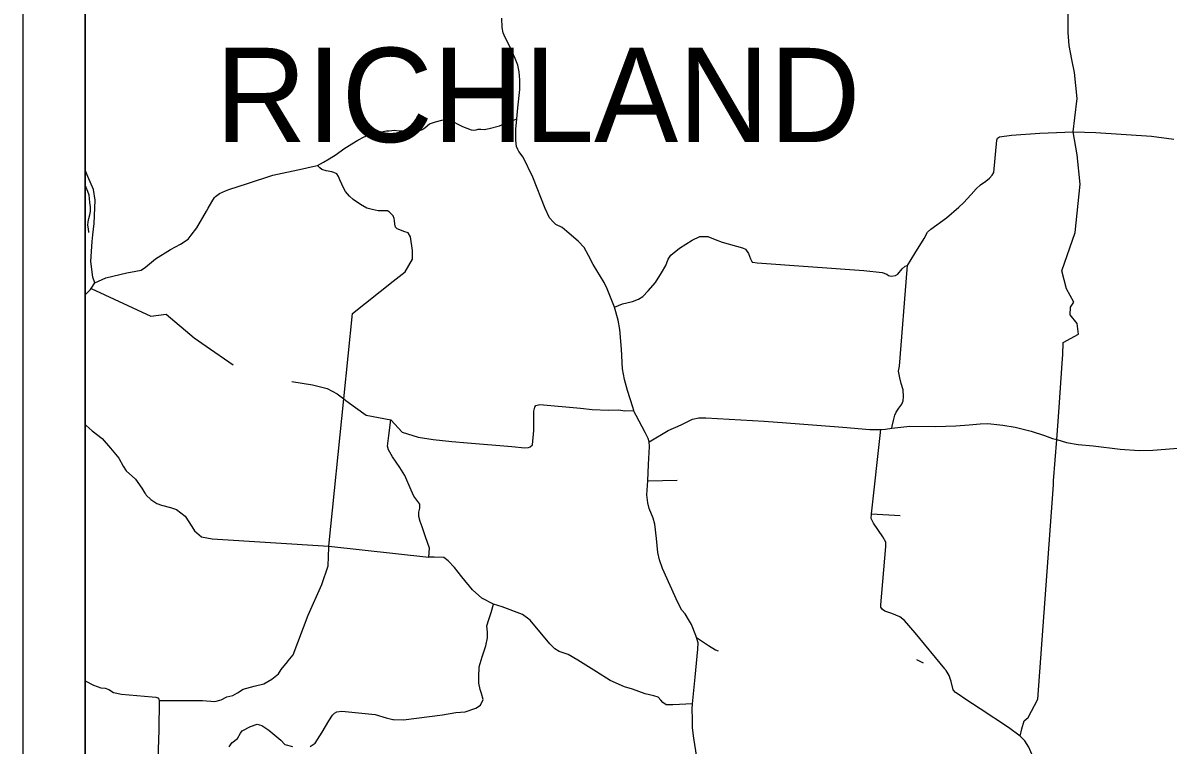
# Model space of a CAD drawing. Extents: x -22 to 431, y -18 to 160.
# Drawn here: x -21.978 to -20.139, y 24.992 to 26.152 of the extents above; entities that cross this region are included whole.
import ezdxf

# ---------------------------------------------------------------- set-up
doc = ezdxf.new("R2010")
doc.units = 0
for name, color, linetype in [('GM_X_Adjacent_County_Text', 7, 'Continuous'), ('GM_X_County_Road', 7, 'Continuous'), ('GM_X_County_Road_Text', 7, 'Continuous'), ('GM_X_County_ROW', 7, 'Continuous'), ('GM_X_Minor_River', 7, 'Continuous'), ('GM_X_Minor_River_Text', 7, 'Continuous'), ('GM_X_Section', 7, 'Continuous'), ('GM_X_Township_Subdivision_Text', 7, 'Continuous')]:
    doc.layers.add(name, color=color, linetype=linetype)

msp = doc.modelspace()

# ---------------------------------------------------------------- linework, layer by layer
at = {"layer": 'GM_X_Adjacent_County_Text'}
for points in [[(-21.8776, 25.7159), (-21.8767, 25.7165), (-21.8689, 25.7237), (-21.8678, 25.7255), (-21.8619, 25.7345), (-21.8654, 25.7436), (-21.8684, 25.769), (-21.8666, 25.8007), (-21.8653, 25.8115), (-21.8632, 25.8297), (-21.8619, 25.8548), (-21.8618, 25.8675), (-21.8644, 25.8845), (-21.8736, 25.9051), (-21.8776, 25.9155)], [(-20.9723, 25.4793), (-20.9414, 25.4974), (-20.9209, 25.5063), (-20.9024, 25.5156), (-20.8925, 25.5177), (-20.881, 25.5179), (-20.7873, 25.5121), (-20.7518, 25.5095), (-20.6613, 25.5025), (-20.6178, 25.4992), (-20.6, 25.499), (-20.5928, 25.4996), (-20.5824, 25.5013), (-20.5534, 25.5041), (-20.5121, 25.504), (-20.4798, 25.505), (-20.4585, 25.5063), (-20.4409, 25.5082), (-20.4283, 25.5088), (-20.4044, 25.506), (-20.3845, 25.5028), (-20.3589, 25.4963), (-20.3375, 25.4891), (-20.3245, 25.4846), (-20.3178, 25.4827), (-20.3021, 25.4782), (-20.2834, 25.4751), (-20.2593, 25.4725), (-20.2157, 25.4676), (-20.1856, 25.4655), (-20.1635, 25.4657), (-20.1163, 25.4694)], [(-21.8776, 25.0951), (-21.8645, 25.0883), (-21.8527, 25.0843), (-21.8457, 25.0834), (-21.8395, 25.0813), (-21.8321, 25.0768), (-21.8192, 25.0741), (-21.7698, 25.0696), (-21.7639, 25.069), (-21.7609, 25.0681), (-21.7594, 25.066), (-21.759, 25.0647), (-21.7586, 25.0635), (-21.7595, 25.0163), (-21.7609, 24.9693)]]:
    msp.add_lwpolyline(points, dxfattribs=at)
at = {"layer": 'GM_X_County_Road'}
for points in [[(-20.3081, 25.6189), (-20.3081, 25.619), (-20.3072, 25.6388), (-20.2826, 25.6523), (-20.2849, 25.669), (-20.2959, 25.6832), (-20.2954, 25.6955), (-20.2901, 25.7035), (-20.3019, 25.7251), (-20.3097, 25.7536), (-20.2884, 25.8154), (-20.2799, 25.8932), (-20.2849, 25.9402), (-20.2916, 25.9769)], [(-21.5516, 25.1273), (-21.5436, 25.1373), (-21.5196, 25.2007), (-21.4977, 25.25), (-21.4875, 25.2798), (-21.4866, 25.3101), (-21.4865, 25.3117), (-21.4623, 25.5482), (-21.4483, 25.6855), (-21.3833, 25.7371), (-21.364, 25.7523), (-21.3522, 25.7724), (-21.3519, 25.7865), (-21.3553, 25.8083), (-21.3591, 25.815), (-21.3658, 25.8171)], [(-21.326, 25.2941), (-21.3249, 25.3082), (-21.331, 25.3265), (-21.3363, 25.3427), (-21.3397, 25.351), (-21.3418, 25.3592), (-21.3417, 25.366), (-21.3402, 25.3726), (-21.3405, 25.3789), (-21.3498, 25.3918), (-21.354, 25.4018), (-21.3643, 25.4251), (-21.3722, 25.438), (-21.3842, 25.4549), (-21.3905, 25.4661), (-21.3924, 25.4722), (-21.3899, 25.4896), (-21.3871, 25.5147)], [(-21.7815, 25.3966), (-21.7795, 25.3934), (-21.7723, 25.3865), (-21.7626, 25.3801), (-21.755, 25.3773), (-21.7408, 25.3739), (-21.731, 25.3705), (-21.7171, 25.36), (-21.7063, 25.343), (-21.702, 25.3361), (-21.691, 25.3267), (-21.6739, 25.3235), (-21.4865, 25.3117)], [(-20.3767, 25.0063), (-20.3736, 25.0182), (-20.3699, 25.0313), (-20.3634, 25.0366), (-20.3481, 25.066), (-20.3231, 25.4099), (-20.3231, 25.4101)], [(-21.5165, 24.9901), (-21.5084, 24.9951), (-21.497, 25.0131), (-21.4864, 25.0309), (-21.4806, 25.0404), (-21.4772, 25.0435), (-21.4738, 25.0457), (-21.4658, 25.0467), (-21.412, 25.041), (-21.3946, 25.0359), (-21.3838, 25.0331), (-21.3829, 25.0331)], [(-21.6464, 24.9895), (-21.6419, 24.9955), (-21.6333, 25.0029), (-21.6284, 25.0113), (-21.6254, 25.0149), (-21.6124, 25.0221), (-21.6016, 25.0255), (-21.5938, 25.0235), (-21.5828, 25.0161), (-21.5635, 24.9998), (-21.5572, 24.9931), (-21.5449, 24.9897)]]:
    msp.add_lwpolyline(points, dxfattribs=at)
at = {"layer": 'GM_X_County_ROW'}
msp.add_lwpolyline([(-20.8938, 24.9625), (-20.9005, 25.0031), (-20.9024, 25.02), (-20.9024, 25.0333), (-20.903, 25.0504), (-20.9023, 25.0585), (-20.8984, 25.1014), (-20.8939, 25.1461), (-20.8935, 25.1564), (-20.8961, 25.1651), (-20.897, 25.1684), (-20.9039, 25.1857), (-20.9088, 25.1937), (-20.9143, 25.2028), (-20.9196, 25.209), (-20.926, 25.2211), (-20.9506, 25.2758), (-20.9554, 25.2896), (-20.9583, 25.3014), (-20.9605, 25.3241), (-20.9628, 25.3467), (-20.9656, 25.3565), (-20.9721, 25.372), (-20.9745, 25.3814), (-20.9758, 25.3939), (-20.9745, 25.4165), (-20.9729, 25.4425), (-20.9715, 25.4717), (-20.9723, 25.4793), (-20.9739, 25.4843), (-20.9786, 25.4939), (-20.9928, 25.5214), (-20.9962, 25.5275), (-20.9968, 25.5294), (-20.9985, 25.5348), (-21.0068, 25.5614), (-21.0119, 25.5795), (-21.0148, 25.5965), (-21.0167, 25.6281), (-21.0192, 25.6598), (-21.0221, 25.6747), (-21.0277, 25.6957), (-21.0395, 25.7251), (-21.0446, 25.7352), (-21.0618, 25.7637), (-21.0696, 25.7783), (-21.0764, 25.7912), (-21.0862, 25.8015), (-21.1042, 25.8169), (-21.1118, 25.8233), (-21.1218, 25.8282), (-21.1261, 25.8325), (-21.132, 25.8391), (-21.1393, 25.8537), (-21.159, 25.9042), (-21.1744, 25.9364), (-21.1811, 25.9457), (-21.1831, 25.9489), (-21.1851, 25.9537), (-21.186, 25.9638), (-21.186, 25.9814), (-21.1846, 25.9977), (-21.1829, 26.0155), (-21.18, 26.0449), (-21.1797, 26.0607), (-21.1808, 26.0732), (-21.183, 26.0839), (-21.187, 26.0946), (-21.1968, 26.1162), (-21.2035, 26.1287), (-21.2064, 26.136), (-21.208, 26.1446), (-21.2084, 26.1594)], dxfattribs=at)
at = {"layer": 'GM_X_Minor_River'}
msp.add_lwpolyline([(-21.8719, 25.8154), (-21.8725, 25.821), (-21.8731, 25.827), (-21.8727, 25.8325), (-21.8718, 25.8377), (-21.8701, 25.8437), (-21.8693, 25.8492), (-21.869, 25.8568), (-21.8699, 25.8635), (-21.8705, 25.8699), (-21.8712, 25.8754), (-21.8735, 25.8811), (-21.8762, 25.8875), (-21.8776, 25.8912)], dxfattribs=at)
at = {"layer": 'GM_X_Minor_River_Text'}
for points in [[(-20.2916, 25.9769), (-20.2886, 25.9994), (-20.2849, 26.0306), (-20.2894, 26.0723), (-20.2936, 26.0931), (-20.2979, 26.1158), (-20.2996, 26.1363), (-20.2996, 26.1782), (-20.3006, 26.2362)], [(-21.8619, 25.7345), (-21.8445, 25.7427), (-21.8108, 25.7505), (-21.7965, 25.7533), (-21.7879, 25.7551), (-21.7806, 25.7598), (-21.7645, 25.7729), (-21.7408, 25.7879), (-21.7247, 25.7968), (-21.7124, 25.8046), (-21.7077, 25.8109), (-21.6986, 25.823), (-21.6826, 25.8498), (-21.6799, 25.8543), (-21.6744, 25.8647), (-21.6699, 25.8716), (-21.6682, 25.8731), (-21.6617, 25.8778), (-21.6525, 25.8824), (-21.6469, 25.8842), (-21.6171, 25.8943), (-21.5763, 25.9074), (-21.5288, 25.9174), (-21.5146, 25.9206), (-21.5047, 25.9231), (-21.4951, 25.9281), (-21.4861, 25.9335), (-21.4746, 25.9408), (-21.4622, 25.9496), (-21.4495, 25.9579), (-21.4397, 25.9638), (-21.4298, 25.9688), (-21.4203, 25.9727), (-21.4163, 25.9739), (-21.4111, 25.9752), (-21.4048, 25.9766), (-21.3939, 25.9784), (-21.3895, 25.9786), (-21.381, 25.9795), (-21.3738, 25.9788), (-21.3598, 25.9787), (-21.3526, 25.9788), (-21.3499, 25.9784), (-21.3442, 25.9783), (-21.3414, 25.9788), (-21.3365, 25.981), (-21.334, 25.9823), (-21.3316, 25.984), (-21.325, 25.99), (-21.3152, 25.9933), (-21.305, 25.996), (-21.3005, 25.997), (-21.2925, 25.9961), (-21.2718, 25.9857), (-21.2646, 25.9831), (-21.2579, 25.9805), (-21.2545, 25.9796), (-21.25, 25.9803), (-21.2466, 25.9815), (-21.2426, 25.9812), (-21.2371, 25.9808), (-21.2291, 25.9824), (-21.2123, 25.9869), (-21.2059, 25.9892), (-21.2025, 25.9908), (-21.1976, 25.9925), (-21.1946, 25.9935), (-21.1846, 25.9977)], [(-20.5574, 25.7623), (-20.5458, 25.7815), (-20.5305, 25.8057), (-20.525, 25.816), (-20.5199, 25.8205), (-20.4946, 25.839), (-20.4749, 25.856), (-20.4674, 25.8631), (-20.4553, 25.8762), (-20.4469, 25.8855), (-20.4401, 25.8921), (-20.4318, 25.8976), (-20.4258, 25.9026), (-20.4214, 25.9073), (-20.4188, 25.9115), (-20.4137, 25.9634), (-20.4128, 25.9667), (-20.4098, 25.9691), (-20.3906, 25.9718), (-20.345, 25.9747), (-20.2916, 25.9769), (-20.2552, 25.9758), (-20.1658, 25.9698), (-20.1296, 25.9655)], [(-21.3658, 25.8171), (-21.3696, 25.8184), (-21.3766, 25.8213), (-21.3795, 25.8238), (-21.3803, 25.8289), (-21.3809, 25.8346), (-21.3813, 25.8378), (-21.3832, 25.8423), (-21.3891, 25.848), (-21.3924, 25.85), (-21.3994, 25.85), (-21.4073, 25.8503), (-21.417, 25.8521), (-21.4254, 25.8547), (-21.4356, 25.8605), (-21.4473, 25.8682), (-21.4534, 25.8738), (-21.4597, 25.8814), (-21.463, 25.8872), (-21.4657, 25.8931), (-21.4685, 25.8997), (-21.4709, 25.9055), (-21.4737, 25.9097), (-21.4785, 25.9119), (-21.4817, 25.9128), (-21.4908, 25.9143), (-21.4977, 25.9167), (-21.5007, 25.9191), (-21.5047, 25.9231)], [(-21.0277, 25.6957), (-21.0151, 25.7006), (-20.9988, 25.7046), (-20.989, 25.7082), (-20.9824, 25.7126), (-20.9737, 25.7215), (-20.9619, 25.735), (-20.9521, 25.7504), (-20.9455, 25.7625), (-20.9415, 25.7724), (-20.9372, 25.7792), (-20.9232, 25.7904), (-20.9031, 25.8031), (-20.8905, 25.809), (-20.8778, 25.8087), (-20.8662, 25.8043), (-20.8547, 25.7998), (-20.8221, 25.7909), (-20.8172, 25.7884), (-20.8128, 25.7814), (-20.8096, 25.7729), (-20.8065, 25.7678), (-20.8061, 25.7677), (-20.8059, 25.7677)], [(-20.8059, 25.7677), (-20.7988, 25.7666), (-20.6274, 25.7541), (-20.5979, 25.7511), (-20.5903, 25.7484), (-20.588, 25.7463), (-20.5833, 25.7452), (-20.5766, 25.7461), (-20.5731, 25.7486), (-20.5659, 25.757), (-20.5611, 25.7611), (-20.5574, 25.7623)], [(-20.5824, 25.5013), (-20.5818, 25.5045), (-20.5797, 25.5136), (-20.5779, 25.5218), (-20.5754, 25.5269), (-20.5711, 25.5333), (-20.5665, 25.5396), (-20.5644, 25.5449), (-20.5639, 25.5516), (-20.5645, 25.5627), (-20.5673, 25.5728), (-20.5698, 25.5821), (-20.5717, 25.5929), (-20.5704, 25.6009), (-20.5581, 25.7562), (-20.5574, 25.7623)], [(-21.8678, 25.7255), (-21.7723, 25.6811), (-21.7477, 25.684), (-21.7026, 25.6463), (-21.6835, 25.633)], [(-21.6835, 25.633), (-21.6835, 25.6329), (-21.64, 25.6027)], [(-20.3231, 25.4101), (-20.3227, 25.4167), (-20.3178, 25.4827), (-20.3145, 25.5267), (-20.3083, 25.6132), (-20.3081, 25.6189)], [(-21.5459, 25.5758), (-21.5127, 25.5709), (-21.4889, 25.5648), (-21.4731, 25.5565), (-21.4623, 25.5482), (-21.4589, 25.5455), (-21.4434, 25.5342), (-21.4267, 25.522), (-21.3871, 25.5147), (-21.3685, 25.4948), (-21.343, 25.4864), (-21.3191, 25.4827), (-21.289, 25.4798), (-21.264, 25.4776), (-21.1926, 25.4717), (-21.1716, 25.4697), (-21.1659, 25.4699), (-21.1631, 25.471), (-21.1595, 25.4744), (-21.1574, 25.4972), (-21.1574, 25.5283), (-21.1559, 25.5351), (-21.1542, 25.5376), (-21.1474, 25.5391), (-21.0821, 25.5331), (-21.0637, 25.531), (-21.0372, 25.5299), (-21.0209, 25.5307), (-21.0109, 25.5292), (-20.9968, 25.5294)], [(-21.8776, 25.5072), (-21.876, 25.5056), (-21.8665, 25.4969), (-21.8504, 25.4847), (-21.8368, 25.4692), (-21.8237, 25.4527), (-21.8165, 25.44), (-21.8117, 25.4328), (-21.7968, 25.4193), (-21.7865, 25.4046), (-21.7816, 25.3967), (-21.7815, 25.3966)], [(-20.4968, 25.1136), (-20.4975, 25.1144), (-20.545, 25.1724), (-20.5623, 25.1921), (-20.5697, 25.198), (-20.5823, 25.2035), (-20.5935, 25.2071), (-20.5977, 25.2101), (-20.6, 25.2137), (-20.6004, 25.2175), (-20.5923, 25.311), (-20.5923, 25.3179), (-20.5967, 25.3266), (-20.6121, 25.3488), (-20.6155, 25.3563), (-20.6149, 25.3637), (-20.6, 25.499)], [(-20.9745, 25.4165), (-20.9269, 25.4175)], [(-20.6149, 25.3637), (-20.5691, 25.3607)], [(-21.4865, 25.3117), (-21.326, 25.2941)], [(-21.2218, 25.2183), (-21.2409, 25.2282), (-21.2557, 25.2416), (-21.2728, 25.2621), (-21.2844, 25.2773), (-21.2946, 25.2879), (-21.302, 25.2932), (-21.3175, 25.2939), (-21.326, 25.2941)], [(-21.3829, 25.0331), (-21.3828, 25.0331), (-21.3664, 25.0325), (-21.3037, 25.0409), (-21.2823, 25.0444), (-21.2676, 25.0453), (-21.2502, 25.0514), (-21.2428, 25.0563), (-21.2386, 25.0653), (-21.2411, 25.0749), (-21.2432, 25.0816), (-21.2455, 25.0914), (-21.2455, 25.1011), (-21.2453, 25.118), (-21.2402, 25.1337), (-21.2346, 25.1516), (-21.2318, 25.1643), (-21.2318, 25.1734), (-21.2325, 25.1834), (-21.2297, 25.1937), (-21.2257, 25.2052), (-21.2218, 25.2183)], [(-21.0565, 25.1096), (-21.0867, 25.1287), (-21.102, 25.1376), (-21.1168, 25.1425), (-21.1238, 25.1469), (-21.1316, 25.155), (-21.1629, 25.1928), (-21.1754, 25.2019), (-21.2083, 25.2142), (-21.2218, 25.2183)], [(-20.8961, 25.1651), (-20.8767, 25.152), (-20.8655, 25.1452), (-20.8615, 25.1437)], [(-21.7586, 25.0635), (-21.6895, 25.0636), (-21.6692, 25.0621), (-21.6594, 25.0646), (-21.6501, 25.0695), (-21.6404, 25.0716), (-21.6333, 25.0762), (-21.6238, 25.0819), (-21.6062, 25.0866), (-21.5907, 25.0904), (-21.578, 25.0978), (-21.5672, 25.1067), (-21.5627, 25.1134), (-21.5526, 25.126), (-21.5516, 25.1273)], [(-20.9023, 25.0585), (-20.9343, 25.0568), (-20.9449, 25.0568), (-20.9502, 25.0604), (-20.9531, 25.0642), (-20.9574, 25.0689), (-20.9646, 25.071), (-20.9785, 25.0744), (-20.9987, 25.0819), (-21.0116, 25.0855), (-21.0349, 25.096), (-21.0565, 25.1096)], [(-20.1897, 24.7207), (-20.3206, 24.8655), (-20.3295, 24.8778), (-20.3464, 24.9387), (-20.3527, 24.9632), (-20.3575, 24.9778), (-20.3626, 24.989), (-20.369, 24.9988), (-20.3767, 25.0063), (-20.3952, 25.0202), (-20.4407, 25.0505), (-20.4653, 25.0663), (-20.4746, 25.0727), (-20.4805, 25.0767), (-20.4839, 25.0809), (-20.487, 25.0943), (-20.4906, 25.104), (-20.4953, 25.1118), (-20.4968, 25.1136)]]:
    msp.add_lwpolyline(points, dxfattribs=at)
at = {"layer": 'GM_X_Section'}
for p, q in [((-21.9776, 29.1642), (-21.9776, 22.1642)), ((-21.8776, 29.0642), (-21.8776, 22.2642)), ((-21.8776, 22.2642), (-21.8776, 29.0642))]:
    msp.add_line(p, q, dxfattribs=at)
at = {"layer": 'GM_X_Township_Subdivision_Text'}
msp.add_lwpolyline([(-20.5314, 25.1237), (-20.5425, 25.1291)], dxfattribs=at)

# ---------------------------------------------------------------- texts
at = {"layer": 'GM_X_County_Road_Text'}
msp.add_text('RICHLAND', height=0.15152, rotation=0, dxfattribs=at).set_placement((-21.6685, 25.9605))

doc.saveas('drawing.dxf')
